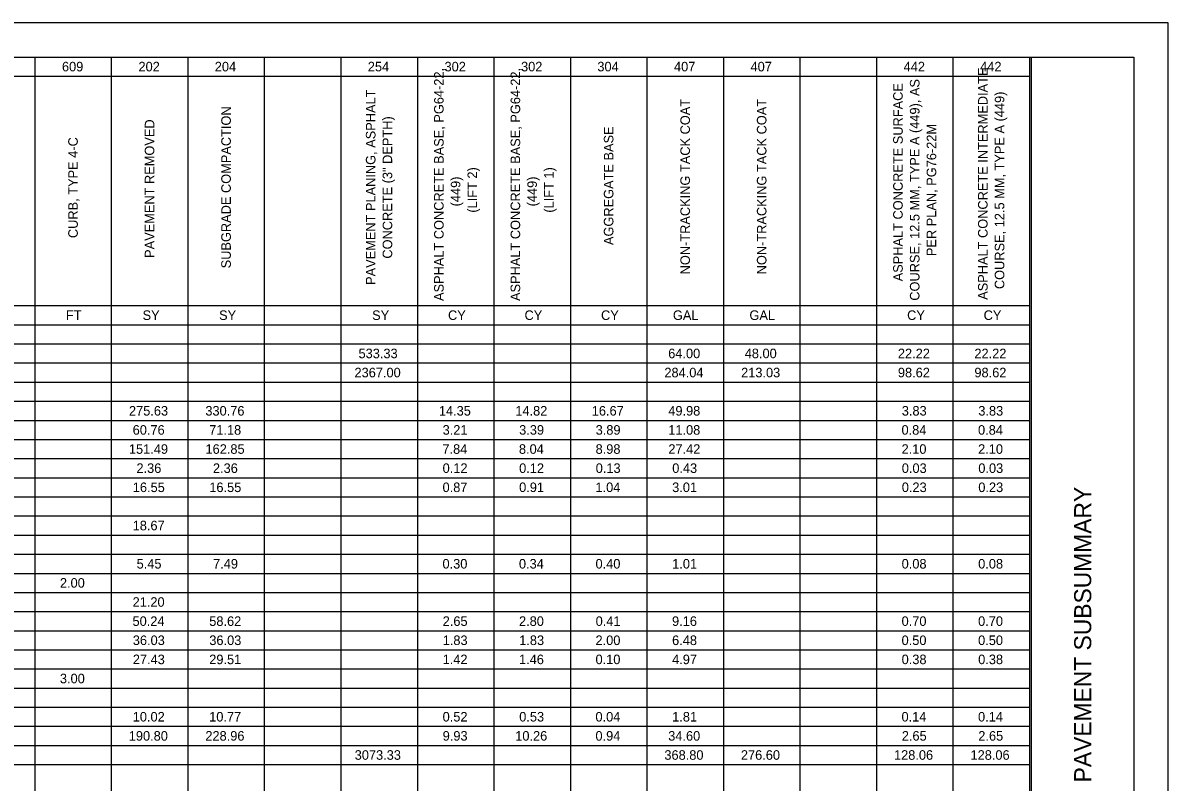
# Model space of a CAD drawing. Extents: x 0 to 34, y 0 to 22.
# Drawn here: x 17.24 to 34, y 10.88 to 22 of the extents above; entities that cross this region are included whole.
import ezdxf

# ---------------------------------------------------------------- set-up
doc = ezdxf.new("R2010")
doc.units = 0
for name, color, linetype in [('SH_Border', 7, 'Continuous'), ('SH_Cut_Line', 7, 'Continuous'), ('SH_Data', 7, 'Continuous'), ('SH_Text', 7, 'Continuous')]:
    doc.layers.add(name, color=color, linetype=linetype)

msp = doc.modelspace()

# ---------------------------------------------------------------- linework, layer by layer
at = {"layer": 'SH_Border'}
msp.add_line((32, 0.5), (32, 21.5), dxfattribs=at)
msp.add_lwpolyline([(1.5, 21.5), (33.5, 21.5), (33.5, 0.5), (1.5, 0.5)], close=True, dxfattribs=at)
at = {"layer": 'SH_Cut_Line'}
msp.add_lwpolyline([(0, 0), (34, 0), (34, 22), (0, 22)], close=True, dxfattribs=at)
at = {"layer": 'SH_Data'}
for p, q in [((1.5, 21.5), (31.971, 21.5)), ((17.411, 21.5), (17.411, 0.5)), ((18.531, 21.5), (18.531, 0.5)), ((19.651, 21.5), (19.651, 0.5)), ((20.771, 21.5), (20.771, 0.5)), ((21.891, 21.5), (21.891, 0.5)), ((23.011, 21.5), (23.011, 0.5)), ((24.131, 21.5), (24.131, 0.78)), ((25.251, 21.5), (25.251, 0.5)), ((26.371, 21.5), (26.371, 0.5)), ((27.491, 21.5), (27.491, 0.78)), ((28.611, 21.5), (28.611, 0.5)), ((29.731, 21.5), (29.731, 0.5)), ((30.851, 21.5), (30.851, 0.5)), ((31.971, 21.5), (31.971, 0.5)), ((11.811, 21.22), (31.971, 21.22)), ((7.331, 17.86), (31.971, 17.86)), ((1.5, 17.58), (31.971, 17.58)), ((1.5, 17.3), (31.971, 17.3)), ((1.5, 17.02), (31.971, 17.02)), ((1.5, 16.74), (31.971, 16.74)), ((1.5, 16.46), (31.971, 16.46)), ((1.5, 16.18), (31.971, 16.18)), ((1.5, 15.9), (31.971, 15.9)), ((1.5, 15.62), (31.971, 15.62)), ((1.5, 15.34), (31.971, 15.34)), ((1.5, 15.06), (31.971, 15.06)), ((1.5, 14.78), (31.971, 14.78)), ((1.5, 14.5), (31.971, 14.5)), ((1.5, 14.22), (31.971, 14.22)), ((1.5, 13.94), (31.971, 13.94)), ((1.5, 13.66), (31.971, 13.66)), ((1.5, 13.38), (31.971, 13.38)), ((1.5, 13.1), (31.971, 13.1)), ((1.5, 12.82), (31.971, 12.82)), ((1.5, 12.54), (31.971, 12.54)), ((1.5, 12.26), (31.971, 12.26)), ((1.5, 11.98), (31.971, 11.98)), ((1.5, 11.7), (31.971, 11.7)), ((1.5, 11.42), (31.971, 11.42)), ((1.5, 11.14), (31.971, 11.14))]:
    msp.add_line(p, q, dxfattribs=at)

# ---------------------------------------------------------------- texts
msp.add_text('PAVEMENT SUBSUMMARY', height=0.25, rotation=90, dxfattribs=at).set_placement((32.875, 10.879))
at = {"layer": 'SH_Text'}
for s, p in [('609', (17.809, 21.29)), ('202', (18.929, 21.29)), ('204', (20.046, 21.29)), ('254', (22.286, 21.29)), ('302', (23.409, 21.29)), ('302', (24.529, 21.29)), ('304', (25.646, 21.29)), ('407', (26.768, 21.29)), ('407', (27.888, 21.29)), ('442', (30.129, 21.29)), ('442', (31.249, 21.29)), ('FT', (17.867, 17.65)), ('SY', (18.989, 17.65)), ('SY', (20.109, 17.65)), ('SY', (22.349, 17.65)), ('CY', (23.46, 17.65)), ('CY', (24.58, 17.65)), ('CY', (25.7, 17.65)), ('GAL', (26.752, 17.65)), ('GAL', (27.872, 17.65)), ('CY', (30.18, 17.65)), ('CY', (31.3, 17.65)), ('533.33', (22.15, 17.09)), ('64.00', (26.683, 17.09)), ('48.00', (27.803, 17.09)), ('22.22', (30.045, 17.09)), ('22.22', (31.165, 17.09)), ('2367.00', (22.091, 16.81)), ('284.04', (26.627, 16.81)), ('213.03', (27.75, 16.81)), ('98.62', (30.045, 16.81)), ('98.62', (31.165, 16.81)), ('275.63', (18.79, 16.25)), ('330.76', (19.908, 16.25)), ('14.35', (23.326, 16.25)), ('14.82', (24.445, 16.25)), ('16.67', (25.564, 16.25)), ('49.98', (26.684, 16.25)), ('3.83', (30.102, 16.25)), ('3.83', (31.222, 16.25)), ('60.76', (18.844, 15.97)), ('71.18', (19.964, 15.97)), ('3.21', (23.381, 15.97)), ('3.39', (24.501, 15.97)), ('3.89', (25.621, 15.97)), ('11.08', (26.684, 15.97)), ('0.84', (30.098, 15.97)), ('0.84', (31.218, 15.97)), ('151.49', (18.789, 15.69)), ('162.85', (19.91, 15.69)), ('7.84', (23.378, 15.69)), ('8.04', (24.498, 15.69)), ('8.98', (25.62, 15.69)), ('27.42', (26.685, 15.69)), ('2.10', (30.099, 15.69)), ('2.10', (31.219, 15.69)), ('2.36', (18.899, 15.41)), ('2.36', (20.019, 15.41)), ('0.12', (23.381, 15.41)), ('0.12', (24.501, 15.41)), ('0.13', (25.622, 15.41)), ('0.43', (26.742, 15.41)), ('0.03', (30.102, 15.41)), ('0.03', (31.222, 15.41)), ('16.55', (18.846, 15.13)), ('16.55', (19.966, 15.13)), ('0.87', (23.38, 15.13)), ('0.91', (24.501, 15.13)), ('1.04', (25.618, 15.13)), ('3.01', (26.741, 15.13)), ('0.23', (30.102, 15.13)), ('0.23', (31.222, 15.13)), ('18.67', (18.844, 14.57)), ('5.45', (18.902, 14.01)), ('7.49', (20.021, 14.01)), ('0.30', (23.379, 14.01)), ('0.34', (24.498, 14.01)), ('0.40', (25.619, 14.01)), ('1.01', (26.741, 14.01)), ('0.08', (30.1, 14.01)), ('0.08', (31.22, 14.01)), ('2.00', (17.779, 13.73)), ('21.20', (18.843, 13.45)), ('50.24', (18.842, 13.17)), ('58.62', (19.965, 13.17)), ('2.65', (23.382, 13.17)), ('2.80', (24.499, 13.17)), ('0.41', (25.621, 13.17)), ('9.16', (26.739, 13.17)), ('0.70', (30.099, 13.17)), ('0.70', (31.219, 13.17)), ('36.03', (18.846, 12.89)), ('36.03', (19.966, 12.89)), ('1.83', (23.382, 12.89)), ('1.83', (24.502, 12.89)), ('2.00', (25.619, 12.89)), ('6.48', (26.74, 12.89)), ('0.50', (30.099, 12.89)), ('0.50', (31.219, 12.89)), ('27.43', (18.846, 12.61)), ('29.51', (19.965, 12.61)), ('1.42', (23.381, 12.61)), ('1.46', (24.499, 12.61)), ('0.10', (25.619, 12.61)), ('4.97', (26.74, 12.61)), ('0.38', (30.1, 12.61)), ('0.38', (31.22, 12.61)), ('3.00', (17.779, 12.33)), ('10.02', (18.845, 11.77)), ('10.77', (19.964, 11.77)), ('0.52', (23.381, 11.77)), ('0.53', (24.502, 11.77)), ('0.04', (25.618, 11.77)), ('1.81', (26.741, 11.77)), ('0.14', (30.098, 11.77)), ('0.14', (31.218, 11.77)), ('190.80', (18.787, 11.49)), ('228.96', (19.908, 11.49)), ('9.93', (23.382, 11.49)), ('10.26', (24.444, 11.49)), ('0.94', (25.618, 11.49)), ('34.60', (26.683, 11.49)), ('2.65', (30.102, 11.49)), ('2.65', (31.222, 11.49)), ('3073.33', (22.094, 11.21)), ('368.80', (26.627, 11.21)), ('276.60', (27.747, 11.21)), ('128.06', (29.988, 11.21)), ('128.06', (31.108, 11.21))]:
    msp.add_text(s, height=0.14, dxfattribs=at).set_placement(p)
for s, p in [('ASPHALT CONCRETE BASE, PG64-22, ', (23.396, 17.928)), ('ASPHALT CONCRETE BASE, PG64-22, ', (24.516, 17.928)), ('ASPHALT CONCRETE INTERMEDIATE ', (31.358, 17.945)), ('COURSE, 12.5 MM, TYPE A (449), AS ', (30.361, 17.932)), ('PAVEMENT PLANING, ASPHALT ', (22.398, 18.163)), ('ASPHALT CONCRETE SURFACE ', (30.116, 18.216)), ('COURSE, 12.5 MM, TYPE A (449)', (31.603, 18.102)), ('NON-TRACKING TACK COAT', (27.001, 18.318)), ('NON-TRACKING TACK COAT', (28.121, 18.318)), ('SUBGRADE COMPACTION', (20.281, 18.406)), ('CONCRETE (3" DEPTH)', (22.643, 18.548)), ('PAVEMENT REMOVED', (19.161, 18.559)), ('AGGREGATE BASE', (25.881, 18.747)), ('PER PLAN, PG76-22M', (30.606, 18.585)), ('CURB, TYPE 4-C', (18.041, 18.849)), ('(LIFT 2)', (23.886, 19.221)), ('(LIFT 1)', (25.006, 19.221)), ('(449)', (23.641, 19.313)), ('(449)', (24.761, 19.313))]:
    msp.add_text(s, height=0.14, rotation=90, dxfattribs=at).set_placement(p)

doc.saveas('drawing.dxf')
